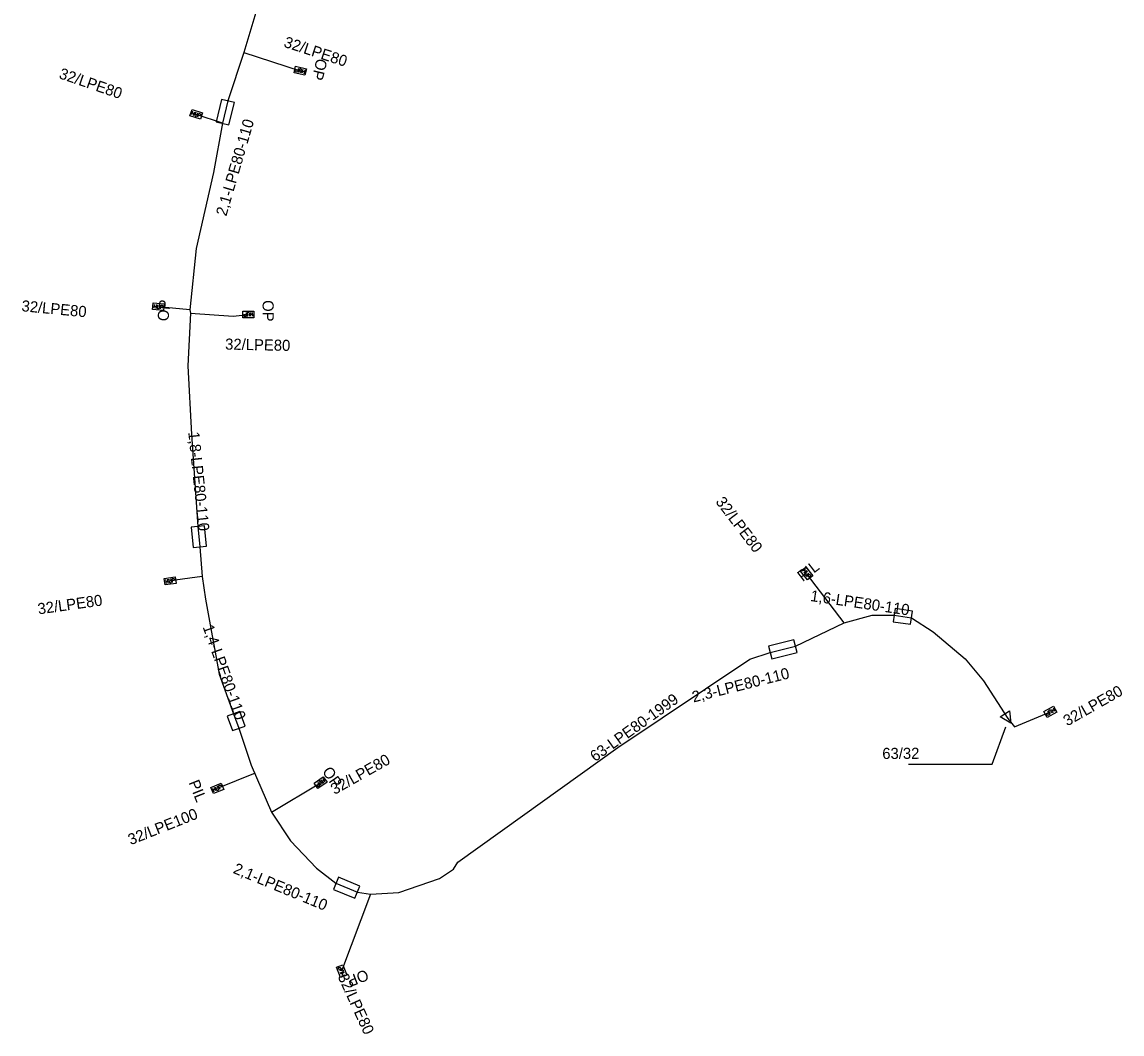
# Model space of a CAD drawing. Extents: x -762509 to -761250, y -1153000 to -1152256.
# Drawn here: x -761787.8 to -761688.6, y -1152437.9 to -1152346.7 of the extents above; entities that cross this region are included whole.
import ezdxf

# ---------------------------------------------------------------- set-up
doc = ezdxf.new("R2010")
doc.units = 0
for name, color, linetype in [('Vrstva 21', 7, 'Continuous'), ('Vrstva 26', 7, 'Continuous'), ('Vrstva 29', 7, 'Continuous'), ('Vrstva 31', 7, 'Continuous'), ('Vrstva 32', 7, 'Continuous')]:
    doc.layers.add(name, color=color, linetype=linetype)

msp = doc.modelspace()

# ---------------------------------------------------------------- linework, layer by layer
at = {"layer": 'Vrstva 21'}
msp.add_lwpolyline([(-761766.55, -1152345.22), (-761767.81, -1152349.42), (-761769.24, -1152353.8), (-761769.73, -1152355.82), (-761770.55, -1152360.26), (-761772.11, -1152367.11), (-761772.67, -1152372.63), (-761772.63, -1152372.94), (-761772.85, -1152377.7), (-761772.54, -1152383.89), (-761771.95, -1152392.17), (-761771.76, -1152394), (-761771.55, -1152396.67), (-761771.27, -1152398.74), (-761770.02, -1152405.49), (-761768.73, -1152409.07), (-761768.27, -1152410.37), (-761767.15, -1152413.69), (-761765.31, -1152417.94), (-761763.59, -1152420.51), (-761761.25, -1152422.99), (-761759.5, -1152424.35), (-761757.57, -1152425.15), (-761756.39, -1152425.33), (-761753.83, -1152425.18), (-761750.17, -1152423.93), (-761748.92, -1152423.07), (-761748.53, -1152422.43), (-761742.68, -1152418.27), (-761734.08, -1152412.11), (-761722.18, -1152404.13), (-761720.35, -1152403.54), (-761718.09, -1152402.97), (-761713.69, -1152400.85), (-761711.15, -1152400.16), (-761709.19, -1152400.17), (-761707.63, -1152400.4), (-761705.66, -1152401.68), (-761702.77, -1152404.12), (-761701.12, -1152406.1), (-761698.94, -1152409.48)], dxfattribs=at)
at = {"layer": 'Vrstva 26'}
msp.add_lwpolyline([(-761698.79, -1152408.789), (-761698.669, -1152409.9), (-761699.631, -1152409.331)], close=True, dxfattribs=at)
msp.add_lwpolyline([(-761707.9, -1152413.6), (-761700.35, -1152413.6), (-761699.1, -1152410.24)], dxfattribs=at)
at = {"layer": 'Vrstva 29'}
for points in [[(-761769.82, -1152353.66), (-761770.31, -1152355.68), (-761769.15, -1152355.96), (-761768.66, -1152353.94)], [(-761772.55, -1152392.23), (-761772.36, -1152394.06), (-761771.16, -1152393.94), (-761771.35, -1152392.11)], [(-761709.28, -1152400.76), (-761707.72, -1152400.99), (-761707.54, -1152399.81), (-761709.1, -1152399.58)], [(-761720.2, -1152404.12), (-761717.94, -1152403.55), (-761718.24, -1152402.39), (-761720.5, -1152402.96)], [(-761769.3, -1152409.27), (-761768.84, -1152410.57), (-761767.7, -1152410.17), (-761768.16, -1152408.87)], [(-761759.73, -1152424.9), (-761757.8, -1152425.7), (-761757.34, -1152424.6), (-761759.27, -1152423.8)]]:
    msp.add_lwpolyline(points, close=True, dxfattribs=at)
at = {"layer": 'Vrstva 31'}
for points in [[(-761767.81, -1152349.42), (-761762.72, -1152351.08)], [(-761769.73, -1152355.82), (-761772.1, -1152355.01)], [(-761772.67, -1152372.63), (-761775.51, -1152372.36)], [(-761772.63, -1152372.94), (-761768.76, -1152373.21), (-761767.41, -1152373.05)], [(-761713.69, -1152400.85), (-761717.07, -1152396.41)], [(-761771.55, -1152396.67), (-761774.45, -1152397.08)], [(-761698.94, -1152409.48), (-761698.32, -1152410.25), (-761695.1, -1152408.89)], [(-761766.78, -1152414.43), (-761770.2, -1152415.79)], [(-761765.31, -1152417.94), (-761760.89, -1152415.28)], [(-761756.39, -1152425.33), (-761758.99, -1152432.28)]]:
    msp.add_lwpolyline(points, dxfattribs=at)
at = {"layer": 'Vrstva 32'}
for p, q in [((-761762.874, -1152350.863), (-761762.955, -1152351.203)), ((-761762.486, -1152350.956), (-761762.567, -1152351.296)), ((-761762.371, -1152351.343), (-761762.29, -1152351.002)), ((-761762.333, -1152351.182), (-761762.528, -1152351.136)), ((-761772.422, -1152354.715), (-761772.535, -1152355.046)), ((-761772.476, -1152354.871), (-761772.285, -1152354.936)), ((-761772.345, -1152355.111), (-761772.232, -1152354.78)), ((-761771.968, -1152355.24), (-761771.855, -1152354.909)), ((-761775.892, -1152372.147), (-761775.925, -1152372.496)), ((-761775.908, -1152372.312), (-761775.708, -1152372.331)), ((-761775.725, -1152372.515), (-761775.692, -1152372.166)), ((-761775.328, -1152372.553), (-761775.295, -1152372.204)), ((-761767.611, -1152372.876), (-761767.608, -1152373.226)), ((-761767.212, -1152372.873), (-761767.209, -1152373.223)), ((-761767.01, -1152373.056), (-761767.211, -1152373.058)), ((-761767.008, -1152373.221), (-761767.011, -1152372.871)), ((-761717.173, -1152395.986), (-761717.452, -1152396.198)), ((-761717.33, -1152396.358), (-761717.051, -1152396.146)), ((-761717.304, -1152396.086), (-761717.183, -1152396.246)), ((-761717.088, -1152396.675), (-761716.809, -1152396.463)), ((-761774.87, -1152396.962), (-761774.821, -1152397.309)), ((-761774.847, -1152397.126), (-761774.648, -1152397.098)), ((-761774.622, -1152397.281), (-761774.671, -1152396.934)), ((-761774.227, -1152397.225), (-761774.276, -1152396.878)), ((-761695.359, -1152408.831), (-761695.192, -1152409.139)), ((-761695.008, -1152408.642), (-761694.842, -1152408.949)), ((-761694.743, -1152408.709), (-761694.92, -1152408.804)), ((-761694.665, -1152408.854), (-761694.831, -1152408.546)), ((-761761.154, -1152415.25), (-761760.956, -1152415.538)), ((-761760.825, -1152415.023), (-761760.627, -1152415.312)), ((-761760.555, -1152415.062), (-761760.72, -1152415.176)), ((-761760.461, -1152415.198), (-761760.66, -1152414.909)), ((-761770.637, -1152415.775), (-761770.507, -1152416.101)), ((-761770.576, -1152415.929), (-761770.389, -1152415.854)), ((-761770.321, -1152416.026), (-761770.45, -1152415.701)), ((-761769.95, -1152415.879), (-761770.079, -1152415.554)), ((-761758.899, -1152432.03), (-761759.226, -1152432.156)), ((-761758.756, -1152432.403), (-761759.082, -1152432.528)), ((-761759.01, -1152432.716), (-761758.683, -1152432.59)), ((-761758.856, -1152432.657), (-761758.928, -1152432.469))]:
    msp.add_line(p, q, dxfattribs=at)
for points in [[(-761762.303, -1152351.487), (-761763.276, -1152351.255), (-761763.136, -1152350.672), (-761762.164, -1152350.904), (-761762.303, -1152351.487)], [(-761762.955, -1152351.203), (-761763.081, -1152351.173), (-761763.118, -1152351.147), (-761763.129, -1152351.128), (-761763.135, -1152351.093), (-761763.123, -1152351.044), (-761763.102, -1152351.015), (-761763.084, -1152351.003), (-761763.039, -1152350.996), (-761762.913, -1152351.026)], [(-761762.663, -1152351.273), (-761762.605, -1152351.029), (-761762.607, -1152350.978), (-761762.63, -1152350.939), (-761762.666, -1152350.912), (-761762.695, -1152350.906), (-761762.739, -1152350.912), (-761762.775, -1152350.938), (-761762.8, -1152350.982), (-761762.859, -1152351.226)], [(-761772.476, -1152354.564), (-761771.53, -1152354.888), (-761771.724, -1152355.455), (-761772.671, -1152355.132), (-761772.476, -1152354.564)], [(-761772.138, -1152354.812), (-761772.22, -1152355.049), (-761772.222, -1152355.1), (-761772.204, -1152355.142), (-761772.169, -1152355.171), (-761772.142, -1152355.181), (-761772.097, -1152355.178), (-761772.058, -1152355.156), (-761772.029, -1152355.114), (-761771.948, -1152354.877)], [(-761771.855, -1152354.909), (-761771.731, -1152354.951), (-761771.697, -1152354.981), (-761771.688, -1152355.001), (-761771.686, -1152355.036), (-761771.702, -1152355.084), (-761771.726, -1152355.11), (-761771.745, -1152355.121), (-761771.79, -1152355.123), (-761771.913, -1152355.081)], [(-761775.98, -1152372.014), (-761774.984, -1152372.108), (-761775.041, -1152372.706), (-761776.037, -1152372.611), (-761775.98, -1152372.014)], [(-761775.593, -1152372.176), (-761775.617, -1152372.426), (-761775.608, -1152372.476), (-761775.58, -1152372.512), (-761775.54, -1152372.533), (-761775.511, -1152372.535), (-761775.468, -1152372.522), (-761775.436, -1152372.492), (-761775.417, -1152372.445), (-761775.393, -1152372.195)], [(-761775.295, -1152372.204), (-761775.165, -1152372.217), (-761775.125, -1152372.237), (-761775.112, -1152372.255), (-761775.101, -1152372.289), (-761775.106, -1152372.339), (-761775.123, -1152372.37), (-761775.139, -1152372.385), (-761775.183, -1152372.398), (-761775.312, -1152372.385)], [(-761766.907, -1152373.346), (-761767.907, -1152373.354), (-761767.912, -1152372.754), (-761766.912, -1152372.746), (-761766.907, -1152373.346)], [(-761767.608, -1152373.226), (-761767.738, -1152373.227), (-761767.78, -1152373.211), (-761767.796, -1152373.195), (-761767.81, -1152373.162), (-761767.81, -1152373.112), (-761767.796, -1152373.079), (-761767.782, -1152373.063), (-761767.74, -1152373.045), (-761767.61, -1152373.044)], [(-761767.308, -1152373.224), (-761767.31, -1152372.973), (-761767.325, -1152372.924), (-761767.356, -1152372.891), (-761767.398, -1152372.875), (-761767.427, -1152372.875), (-761767.469, -1152372.892), (-761767.498, -1152372.925), (-761767.511, -1152372.974), (-761767.509, -1152373.225)], [(-761717.134, -1152395.83), (-761716.528, -1152396.626), (-761717.005, -1152396.989), (-761717.612, -1152396.194), (-761717.134, -1152395.83)], [(-761716.991, -1152396.224), (-761717.191, -1152396.376), (-761717.221, -1152396.417), (-761717.229, -1152396.462), (-761717.217, -1152396.506), (-761717.199, -1152396.529), (-761717.16, -1152396.552), (-761717.117, -1152396.555), (-761717.069, -1152396.536), (-761716.869, -1152396.384)], [(-761716.809, -1152396.463), (-761716.731, -1152396.566), (-761716.719, -1152396.61), (-761716.722, -1152396.632), (-761716.74, -1152396.663), (-761716.78, -1152396.693), (-761716.815, -1152396.702), (-761716.836, -1152396.7), (-761716.875, -1152396.677), (-761716.954, -1152396.573)], [(-761774.987, -1152396.853), (-761773.996, -1152396.713), (-761773.912, -1152397.307), (-761774.903, -1152397.447), (-761774.987, -1152396.853)], [(-761774.573, -1152396.92), (-761774.538, -1152397.169), (-761774.517, -1152397.215), (-761774.482, -1152397.244), (-761774.438, -1152397.255), (-761774.409, -1152397.251), (-761774.37, -1152397.228), (-761774.346, -1152397.191), (-761774.339, -1152397.141), (-761774.374, -1152396.892)], [(-761774.276, -1152396.878), (-761774.147, -1152396.86), (-761774.103, -1152396.871), (-761774.086, -1152396.885), (-761774.068, -1152396.916), (-761774.061, -1152396.965), (-761774.07, -1152397), (-761774.083, -1152397.018), (-761774.122, -1152397.04), (-761774.251, -1152397.059)], [(-761694.517, -1152408.916), (-761695.397, -1152409.392), (-761695.682, -1152408.864), (-761694.803, -1152408.388), (-761694.517, -1152408.916)], [(-761695.192, -1152409.139), (-761695.307, -1152409.201), (-761695.352, -1152409.206), (-761695.373, -1152409.199), (-761695.401, -1152409.177), (-761695.424, -1152409.133), (-761695.428, -1152409.097), (-761695.422, -1152409.076), (-761695.393, -1152409.041), (-761695.279, -1152408.979)], [(-761694.929, -1152408.996), (-761695.048, -1152408.776), (-761695.084, -1152408.739), (-761695.127, -1152408.725), (-761695.172, -1152408.73), (-761695.197, -1152408.744), (-761695.226, -1152408.779), (-761695.236, -1152408.822), (-761695.225, -1152408.871), (-761695.105, -1152409.092)], [(-761770.776, -1152415.696), (-761769.846, -1152415.327), (-761769.625, -1152415.884), (-761770.554, -1152416.254), (-761770.776, -1152415.696)], [(-761760.308, -1152415.244), (-761761.132, -1152415.811), (-761761.472, -1152415.317), (-761760.648, -1152414.75), (-761760.308, -1152415.244)], [(-761760.956, -1152415.538), (-761761.063, -1152415.612), (-761761.107, -1152415.621), (-761761.128, -1152415.617), (-761761.159, -1152415.597), (-761761.187, -1152415.556), (-761761.194, -1152415.521), (-761761.191, -1152415.499), (-761761.166, -1152415.462), (-761761.059, -1152415.388)], [(-761760.708, -1152415.368), (-761760.851, -1152415.161), (-761760.89, -1152415.129), (-761760.934, -1152415.119), (-761760.978, -1152415.129), (-761761.002, -1152415.145), (-761761.027, -1152415.183), (-761761.033, -1152415.227), (-761761.016, -1152415.275), (-761760.874, -1152415.482)], [(-761770.358, -1152415.665), (-761770.265, -1152415.898), (-761770.234, -1152415.938), (-761770.193, -1152415.957), (-761770.148, -1152415.958), (-761770.121, -1152415.947), (-761770.088, -1152415.916), (-761770.073, -1152415.874), (-761770.078, -1152415.824), (-761770.171, -1152415.59)], [(-761770.079, -1152415.554), (-761769.958, -1152415.506), (-761769.913, -1152415.506), (-761769.893, -1152415.515), (-761769.868, -1152415.541), (-761769.849, -1152415.587), (-761769.85, -1152415.623), (-761769.858, -1152415.644), (-761769.891, -1152415.675), (-761770.012, -1152415.723)], [(-761759.091, -1152432.854), (-761759.45, -1152431.921), (-761758.89, -1152431.705), (-761758.531, -1152432.639), (-761759.091, -1152432.854)], [(-761759.226, -1152432.156), (-761759.272, -1152432.035), (-761759.271, -1152431.989), (-761759.262, -1152431.97), (-761759.236, -1152431.945), (-761759.189, -1152431.927), (-761759.154, -1152431.928), (-761759.133, -1152431.936), (-761759.102, -1152431.969), (-761759.056, -1152432.091)], [(-761759.118, -1152432.436), (-761758.884, -1152432.346), (-761758.843, -1152432.315), (-761758.823, -1152432.274), (-761758.822, -1152432.229), (-761758.833, -1152432.202), (-761758.864, -1152432.169), (-761758.905, -1152432.154), (-761758.956, -1152432.158), (-761759.19, -1152432.248)]]:
    msp.add_lwpolyline(points, dxfattribs=at)

# ---------------------------------------------------------------- texts
at = {"layer": 'Vrstva 21'}
msp.add_text('63-LPE80-1999', height=1, rotation=35.61323, dxfattribs=at).set_placement((-761736.14, -1152413.43))
at = {"layer": 'Vrstva 26'}
msp.add_text('63/32', height=1, rotation=0.25755, dxfattribs=at).set_placement((-761710.25, -1152413.14))
at = {"layer": 'Vrstva 29'}
for s, rotation, p in [('2,1-LPE80-110', 73.72425, (-761769.39, -1152364.25)), ('1,8-LPE80-110', 275.92751, (-761772.82, -1152383.68)), ('1,6-LPE80-110', 351.61297, (-761716.78, -1152398.89)), ('1,4-LPE80-110', 289.48613, (-761771.53, -1152401.23)), ('2,3-LPE80-110', 14.15549, (-761727.27, -1152408.05)), ('2,1-LPE80-110', 337.48561, (-761768.84, -1152423.4))]:
    msp.add_text(s, height=1, rotation=rotation, dxfattribs=at).set_placement(p)
at = {"layer": 'Vrstva 31'}
for s, rotation, p in [('32/LPE80', 341.93732, (-761764.27, -1152348.91)), ('32/LPE80', 341.93732, (-761764.27, -1152348.91)), ('32/LPE80', 341.131, (-761784.54, -1152351.74)), ('32/LPE80', 341.131, (-761784.54, -1152351.74)), ('32/LPE80', 354.56919, (-761787.88, -1152372.76)), ('32/LPE80', 354.56919, (-761787.88, -1152372.76)), ('32/LPE80', 358.72723, (-761769.5, -1152376.22)), ('32/LPE80', 358.72723, (-761769.5, -1152376.22)), ('32/LPE80', 307.31134, (-761725.33, -1152389.96)), ('32/LPE80', 307.31134, (-761725.33, -1152389.96)), ('32/LPE80', 8.04711, (-761786.32, -1152400.11)), ('32/LPE80', 8.04711, (-761786.32, -1152400.11)), ('32/LPE80', 29.62409, (-761693.58, -1152410.21)), ('32/LPE80', 29.62409, (-761693.58, -1152410.21)), ('32/LPE80', 29.42988, (-761759.63, -1152416.39)), ('32/LPE80', 29.42988, (-761759.63, -1152416.39)), ('32/LPE100', 21.66087, (-761778.01, -1152420.92)), ('32/LPE100', 21.66087, (-761778.01, -1152420.92)), ('32/LPE80', 294.6099, (-761759.37, -1152432.75)), ('32/LPE80', 294.6099, (-761759.37, -1152432.75))]:
    msp.add_text(s, height=1, rotation=rotation, dxfattribs=at).set_placement(p)
at = {"layer": 'Vrstva 32'}
for s, rotation, p in [('OP', 256.57954, (-761761.24, -1152349.92)), ('OP', 256.57954, (-761761.24, -1152349.92)), ('OP', 84.56919, (-761774.61, -1152373.7)), ('OP', 84.56919, (-761774.61, -1152373.7)), ('OP', 270.45997, (-761766.12, -1152371.77)), ('OP', 270.45997, (-761766.12, -1152371.77)), ('PIL', 37.31134, (-761717.43, -1152397.19)), ('PIL', 37.31134, (-761717.43, -1152397.19)), ('OP', 304.53324, (-761760.79, -1152414.27)), ('OP', 304.53324, (-761760.79, -1152414.27)), ('PIL', 291.66087, (-761772.8, -1152415.26)), ('PIL', 291.66087, (-761772.8, -1152415.26)), ('OP', 201.04212, (-761756.8, -1152432.09)), ('OP', 201.04212, (-761756.8, -1152432.09))]:
    msp.add_text(s, height=1, rotation=rotation, dxfattribs=at).set_placement(p)

doc.saveas('drawing.dxf')
